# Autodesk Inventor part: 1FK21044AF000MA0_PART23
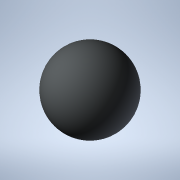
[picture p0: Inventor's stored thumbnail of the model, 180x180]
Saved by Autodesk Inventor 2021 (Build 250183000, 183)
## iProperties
Created: 2025-04
Part Number: 1FK21044AF000MA0_PART23
Material: Generic
Catalog Web Link: www.3dfindit.com
Description: -Servo synchronous motor
Document SubType Name: Modeling
Designer: psAdmin
Mass: 0.137258 g
Surface Area: 1.2868 cm^2
Volume: 0.137258 cm^3
Density: 1 g/cm^3
Appearance: PSOLRGB-212-217-219
Category: PARTsolutions
Title: 1FK21044AF000MA0_PART23
Author: Cadenas PARTsolutions
Comments: Servo synchronous motor
Sending System: PARTsolutions
Preprocessor: ST-DEVELOPER v19.3
PSOL_IDENT_0: {$CADENAS_DATA/23d-libs/siemens_ag/_cat_/39/c4/1fk21044af000ma0.prj},216 {VTYP=3D},{NB=1FK21044AF000
PSOL_IDENT_1: MA0_PART23},{LINA=1FK21044AF000MA0_PART23},{NN=1FK21044AF000MA0_PART23},{NOPRJ=TRUE},{DATE=19.08.202
PSOL_IDENT_2: 5 14:00:33},{GEOMDATE=30.07.2025 02:02:22},{VERSION=},{LINEID=10},{WBVAR=},{WBNUMERIC=}  {NB=1FK2104
PSOL_IDENT_3: 4AF000MA0_PART23},{LINA=1FK21044AF000MA0_PART23},{KT=DUMMY},{PREVIEW=../../../_pool_/cb/72/p_d211_xx
PSOL_IDENT_4: _00434j.png},{DESCSHORT=SIMOTICS S-1FK2 HD, SINAMICS S210 3AC 400V-480V, 1.27 Nm, 3000 rpm},{DESCLON
PSOL_IDENT_5: G=SIMOTICS S-1FK2 HD servo motor M0=1.27 Nm; PN = 0.4 kW at nN=3000 rpm (380-480 V); PN = 0.2 kW at
PSOL_IDENT_6: nN=1500 rpm (200-240 V); degree of protection IP64; cylindrical shaft D19x40mm; absolute encoder 22-
PSOL_IDENT_7: bit + 12-bit multiturn (encoder AM22DQC); with OCC interface; plug size M17, rotatable; SIMOTICS S-1
PSOL_IDENT_8: FK2 servomotorfor a wide range of uses in industrial environments. SIMOTICS S‑1FK2 servomotors are c
PSOL_IDENT_9: ompact synchronous motors with a high dynamic performance that set themselves apart as a result of t
PSOL_IDENT_10: heir high power density, degree of protection and overload capability. The motors are available in t
PSOL_IDENT_11: wo variants: as High Dynamic variant (highest dynamic performance as a result of the low intrinsic m
PSOL_IDENT_12: oment of inertia for applications demanding a high dynamic performance with low moved masses) - and
PSOL_IDENT_13: as Compact variant (precise and stable closed-loop control for medium up to large moved masses as a
PSOL_IDENT_14: result of a medium intrinsic moment of inertia). SIMOTICSS‑1FK2 servomotors fully exploit their stre
PSOL_IDENT_15: ngths in a system with the SINAMICSS210 frequency converter and simple connection using the one cabl
PSOL_IDENT_16: e connection (OCC). Advantages include the short control and positioning times, fast and precise cor
PSOL_IDENT_17: rection of disturbing quantities as well as stable control with a high dynamic performance. The serv
PSOL_IDENT_18: o motors can be configured to address a wide range of requirements. For example with and without hol
PSOL_IDENT_19: ding brake, IP64 or IP65 degree of protection, singleturn or multiturn absolute encoders - to name j
PSOL_IDENT_20: ust a few. Further, the servomotors are available in different shaft heights extending from 20 to 10
PSOL_IDENT_21: 0. A shaft sealing ring is available to achieve an IP65 degree of protection and for subsequent moun
PSOL_IDENT_22: ting at the motor or as spare part. SIMOTICS - the optimum motor for each and every motion control a
PSOL_IDENT_23: pplication.},{INTNO=804766906428},{SUPPLIERALTNO=1FK2104-4AF00-0MA0},{MANUID=1FK21044AF000MA0},{MANU
PSOL_IDENT_24: NAME=Siemens},{MANUTYPEDESC=Synchronous motor 1FK2-HD 1.27 NM},{AAU732=SIMOTICS},{AAO057=S-1FK2},{AA
PSOL_IDENT_25: U734=SIMOTICS S-1FK2 HD servo motor M0=1.27 Nm; PN = 0.4 kW at nN=3000 rpm (380-480 V); PN = 0.2 kW
PSOL_IDENT_26: at nN=1500 rpm (200-240 V); degree of protection IP64; cylindrical shaft D19x40mm; absolute encoder
PSOL_IDENT_27: 22-bit + 12-bit multiturn (encoder AM22DQC); with OCC interface; plug size M17, rotatable;},{AAW338=
PSOL_IDENT_28: Synchronous motor 1FK2-HD 1.27 NM},{AAO742=SIMOTICS},{AAO663=4042948693322},{NOCUPEROU=1},{PRICEQUAN
PSOL_IDENT_29: TITY=1},{QUANTITYMIN=1},{QUANTITYINT=1},{CTN=85015100},{COO=DE},{AAO676=1FK2104-4AF00-0MA0},{AAO677=
PSOL_IDENT_30: Siemens AG},{ORDERUNIT=C62},{CONTENTUNIT=C62}
NB: 1FK21044AF000MA0_PART23
NT: Servo synchronous motor
NBSYN: $MANUID._PART23
LINA: 1FK21044AF000MA0_PART23
CATALOG: SIEMENS
PREVIEW: ../../../_pool_/cb/72/p_d211_xx_00434j.png
DESCSHORT: SIMOTICS S-1FK2 HD, SINAMICS S210 3AC 400V-480V, 1.27 Nm, 3000 rpm
DESCLONG: SIMOTICS S-1FK2 HD servo motor M0=1.27 Nm; PN = 0.4 kW at nN=3000 rpm (380-480 V); PN = 0.2 kW at nN=1500 rpm (200-240 V); degree of protection IP64; cylindrica
INTNO: 804766906428
SUPPLIERALTNO: 1FK2104-4AF00-0MA0
MANUID: 1FK21044AF000MA0
MANUNAME: Siemens
MANUTYPEDESC: Synchronous motor 1FK2-HD 1.27 NM
AAU732: SIMOTICS
AAO057: S-1FK2
AAU734: SIMOTICS S-1FK2 HD servo motor M0=1.27 Nm; PN = 0.4 kW at nN=3000 rpm (380-480 V); PN = 0.2 kW at nN=1500 rpm (200-240 V); degree of protection IP64; cylindrica
AAW338: Synchronous motor 1FK2-HD 1.27 NM
AAO742: SIMOTICS
AAO663: 4042948693322.0
NOCUPEROU: 1
PRICEQUANTITY: 1
QUANTITYMIN: 1
QUANTITYINT: 1
CTN: 85015100
COO: DE
ARTICLENO: 1FK21044AF000MA0_PART23
BOMINFO: 1FK21044AF000MA0_PART23
CREATOR: CADENAS GmbH
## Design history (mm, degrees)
feature "2025_04_17_15_01_28_0038"
body "Solid1"
